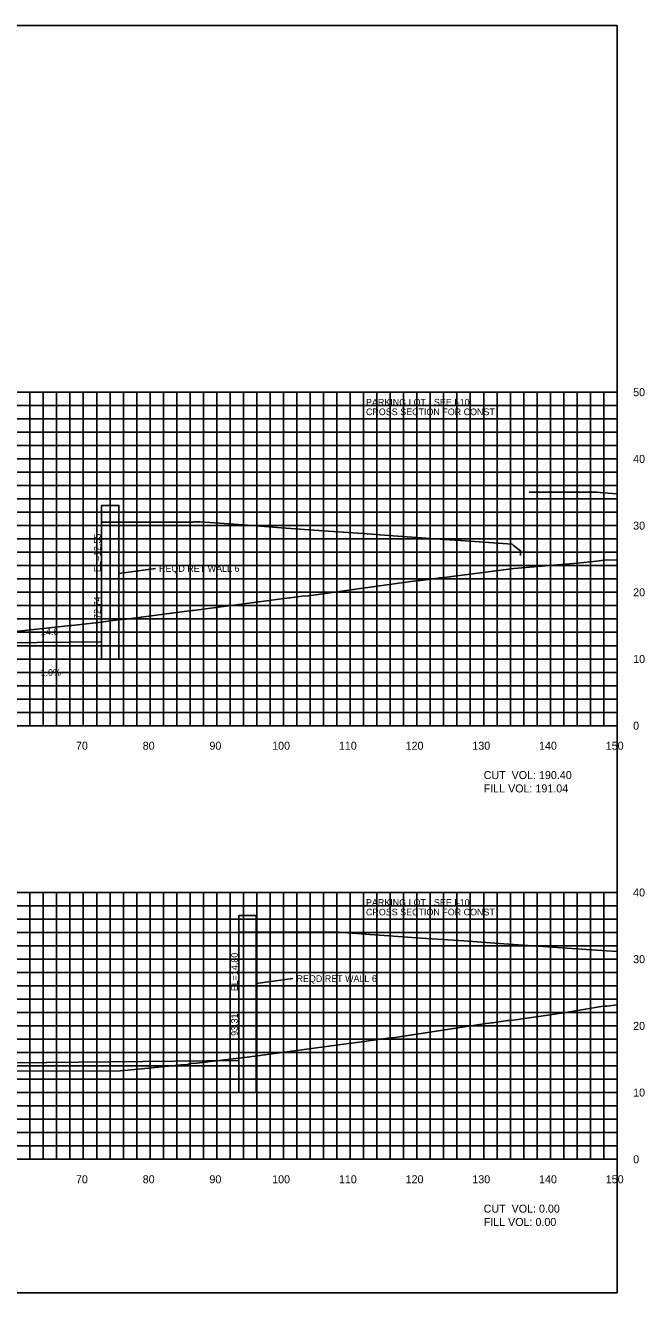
# Model space of a CAD drawing. Extents: x 1797682 to 1802785, y 249453 to 250269.
# Drawn here: x 1802352.3 to 1802445.1, y 250079.4 to 250269.4 of the extents above; entities that cross this region are included whole.
import ezdxf

# ---------------------------------------------------------------- set-up
doc = ezdxf.new("R2010")
doc.units = 0
for name, color, linetype in [('10', 7, 'Continuous'), ('3', 7, 'Continuous'), ('31', 7, 'Continuous'), ('4', 7, 'Continuous'), ('60', 7, 'Continuous'), ('ANNO-TXT', 7, 'Continuous'), ('CL-CNST', 7, 'Continuous'), ('Level 62', 7, 'Continuous'), ('M-ROADS', 7, 'Continuous'), ('WEARING', 7, 'Continuous')]:
    doc.layers.add(name, color=color, linetype=linetype)

msp = doc.modelspace()

# ---------------------------------------------------------------- linework, layer by layer
for p, q in [((1802363.74, 250176.99), (1802363.74, 250178.99)), ((1802384.31, 250114.23), (1802384.31, 250116.23))]:
    msp.add_line(p, q)
msp.add_lwpolyline([(1802141, 250079.43), (1802441, 250079.43), (1802441, 250269.43), (1802141, 250269.43)], close=True)
at = {"layer": '3'}
for p, q in [((1802371.81, 250188), (1802366.33, 250187.26)), ((1802392.4, 250126.52), (1802386.92, 250125.78))]:
    msp.add_line(p, q, dxfattribs=at)
at = {"layer": '60'}
for p, q in [((1802441, 250164.43), (1802441, 250214.43)), ((1802441.06, 250214.43), (1802441, 250214.43)), ((1802441.06, 250204.43), (1802441, 250204.43)), ((1802441.06, 250194.43), (1802441, 250194.43)), ((1802441.06, 250184.43), (1802441, 250184.43)), ((1802441.06, 250174.43), (1802441, 250174.43)), ((1802141, 250164.43), (1802441, 250164.43)), ((1802361, 250164.37), (1802361, 250164.43)), ((1802371, 250164.37), (1802371, 250164.43)), ((1802381, 250164.37), (1802381, 250164.43)), ((1802391, 250164.37), (1802391, 250164.43)), ((1802401, 250164.37), (1802401, 250164.43)), ((1802411, 250164.37), (1802411, 250164.43)), ((1802421, 250164.37), (1802421, 250164.43)), ((1802431, 250164.37), (1802431, 250164.43)), ((1802441, 250164.37), (1802441, 250164.43)), ((1802441.06, 250164.43), (1802441, 250164.43)), ((1802441, 250099.43), (1802441, 250139.43)), ((1802441.06, 250139.43), (1802441, 250139.43)), ((1802441.06, 250129.43), (1802441, 250129.43)), ((1802441.06, 250119.43), (1802441, 250119.43)), ((1802441.06, 250109.43), (1802441, 250109.43)), ((1802141, 250099.43), (1802441, 250099.43)), ((1802361, 250099.37), (1802361, 250099.43)), ((1802371, 250099.37), (1802371, 250099.43)), ((1802381, 250099.37), (1802381, 250099.43)), ((1802391, 250099.37), (1802391, 250099.43)), ((1802401, 250099.37), (1802401, 250099.43)), ((1802411, 250099.37), (1802411, 250099.43)), ((1802421, 250099.37), (1802421, 250099.43)), ((1802431, 250099.37), (1802431, 250099.43)), ((1802441, 250099.37), (1802441, 250099.43)), ((1802441.06, 250099.43), (1802441, 250099.43))]:
    msp.add_line(p, q, dxfattribs=at)
at = {"layer": 'CL-CNST'}
for points in [[(1802366.33, 250194.97), (1802363.74, 250194.97), (1802363.74, 250197.47), (1802366.33, 250197.47)], [(1802363.74, 250174.43), (1802366.33, 250174.43), (1802366.33, 250194.97), (1802363.74, 250194.97)], [(1802386.92, 250133.49), (1802384.31, 250133.49), (1802384.31, 250135.99), (1802386.92, 250135.99)], [(1802384.31, 250109.43), (1802386.92, 250109.43), (1802386.92, 250133.49), (1802384.31, 250133.49)]]:
    msp.add_lwpolyline(points, close=True, dxfattribs=at)
for points in [[(1802366.33, 250194.97), (1802372.49, 250194.95), (1802377.44, 250194.93), (1802377.47, 250194.97), (1802377.51, 250195), (1802378.03, 250195), (1802378.52, 250195), (1802384.3, 250194.58), (1802390.72, 250194.12), (1802395.53, 250193.77), (1802402.91, 250193.24), (1802406.76, 250192.96), (1802415.11, 250192.37), (1802417.52, 250192.19), (1802425.27, 250191.64), (1802425.49, 250191.46), (1802426.54, 250190.67), (1802426.54, 250190.07), (1802426.54, 250189.94)], [(1802234.86, 250176.57), (1802236, 250176.95), (1802237, 250176.99), (1802242, 250177.07), (1802244, 250177.09), (1802244.33, 250177.09), (1802244.5, 250176.59), (1802246.5, 250176.75), (1802291, 250177.73), (1802346.68, 250176.5), (1802348.68, 250176.34), (1802348.85, 250176.84), (1802349.18, 250176.84), (1802363.74, 250176.99)], [(1802386.92, 250133.49), (1802395.6, 250133.47), (1802399.3, 250133.46), (1802404.01, 250133.13), (1802411.67, 250132.6), (1802418.03, 250132.16), (1802424.04, 250131.74), (1802432.08, 250131.18), (1802436.42, 250130.88), (1802441, 250130.56)], [(1802265.51, 250111.95), (1802265.51, 250111.95), (1802269.74, 250113.36), (1802270.74, 250113.4), (1802274.5, 250113.46), (1802274.5, 250113.46), (1802274.51, 250113.46), (1802274.84, 250113.46), (1802274.84, 250113.46), (1802275.01, 250112.97), (1802275.01, 250112.97), (1802276.99, 250113.13), (1802277.01, 250113.12), (1802277.01, 250113.12), (1802291, 250113.43), (1802305, 250113.12), (1802305, 250113.12), (1802307, 250112.96), (1802307, 250112.96), (1802307.16, 250113.46), (1802307.16, 250113.46), (1802307.49, 250113.46), (1802307.52, 250113.46), (1802384.31, 250114.23)]]:
    msp.add_lwpolyline(points, dxfattribs=at)
at = {"layer": 'Level 62'}
for p, q in [((1802141, 250214.43), (1802441, 250214.43)), ((1802353, 250164.43), (1802353, 250214.43)), ((1802355, 250164.43), (1802355, 250214.43)), ((1802357, 250164.43), (1802357, 250214.43)), ((1802359, 250164.43), (1802359, 250214.43)), ((1802361, 250164.43), (1802361, 250214.43)), ((1802363, 250164.43), (1802363, 250214.43)), ((1802365, 250164.43), (1802365, 250214.43)), ((1802367, 250164.43), (1802367, 250214.43)), ((1802369, 250164.43), (1802369, 250214.43)), ((1802371, 250164.43), (1802371, 250214.43)), ((1802373, 250164.43), (1802373, 250214.43)), ((1802375, 250164.43), (1802375, 250214.43)), ((1802377, 250164.43), (1802377, 250214.43)), ((1802379, 250164.43), (1802379, 250214.43)), ((1802381, 250164.43), (1802381, 250214.43)), ((1802383, 250164.43), (1802383, 250214.43)), ((1802385, 250164.43), (1802385, 250214.43)), ((1802387, 250164.43), (1802387, 250214.43)), ((1802389, 250164.43), (1802389, 250214.43)), ((1802391, 250164.43), (1802391, 250214.43)), ((1802393, 250164.43), (1802393, 250214.43)), ((1802395, 250164.43), (1802395, 250214.43)), ((1802397, 250164.43), (1802397, 250214.43)), ((1802399, 250164.43), (1802399, 250214.43)), ((1802401, 250164.43), (1802401, 250214.43)), ((1802403, 250164.43), (1802403, 250214.43)), ((1802405, 250164.43), (1802405, 250214.43)), ((1802407, 250164.43), (1802407, 250214.43)), ((1802409, 250164.43), (1802409, 250214.43)), ((1802411, 250164.43), (1802411, 250214.43)), ((1802413, 250164.43), (1802413, 250214.43)), ((1802415, 250164.43), (1802415, 250214.43)), ((1802417, 250164.43), (1802417, 250214.43)), ((1802419, 250164.43), (1802419, 250214.43)), ((1802421, 250164.43), (1802421, 250214.43)), ((1802423, 250164.43), (1802423, 250214.43)), ((1802425, 250164.43), (1802425, 250214.43)), ((1802427, 250164.43), (1802427, 250214.43)), ((1802429, 250164.43), (1802429, 250214.43)), ((1802431, 250164.43), (1802431, 250214.43)), ((1802433, 250164.43), (1802433, 250214.43)), ((1802435, 250164.43), (1802435, 250214.43)), ((1802437, 250164.43), (1802437, 250214.43)), ((1802439, 250164.43), (1802439, 250214.43)), ((1802441, 250164.43), (1802441, 250214.43)), ((1802141, 250212.43), (1802441, 250212.43)), ((1802141, 250210.43), (1802441, 250210.43)), ((1802141, 250208.43), (1802441, 250208.43)), ((1802141, 250206.43), (1802441, 250206.43)), ((1802141, 250204.43), (1802441, 250204.43)), ((1802141, 250202.43), (1802441, 250202.43)), ((1802141, 250200.43), (1802441, 250200.43)), ((1802141, 250198.43), (1802441, 250198.43)), ((1802141, 250196.43), (1802441, 250196.43)), ((1802141, 250194.43), (1802441, 250194.43)), ((1802141, 250192.43), (1802441, 250192.43)), ((1802141, 250190.43), (1802441, 250190.43)), ((1802141, 250188.43), (1802441, 250188.43)), ((1802141, 250186.43), (1802441, 250186.43)), ((1802141, 250184.43), (1802441, 250184.43)), ((1802141, 250182.43), (1802441, 250182.43)), ((1802141, 250180.43), (1802441, 250180.43)), ((1802141, 250178.43), (1802441, 250178.43)), ((1802141, 250176.43), (1802441, 250176.43)), ((1802141, 250174.43), (1802441, 250174.43)), ((1802141, 250172.43), (1802441, 250172.43)), ((1802141, 250170.43), (1802441, 250170.43)), ((1802141, 250168.43), (1802441, 250168.43)), ((1802141, 250166.43), (1802441, 250166.43)), ((1802141, 250164.43), (1802441, 250164.43)), ((1802141, 250139.43), (1802441, 250139.43)), ((1802353, 250099.43), (1802353, 250139.43)), ((1802355, 250099.43), (1802355, 250139.43)), ((1802357, 250099.43), (1802357, 250139.43)), ((1802359, 250099.43), (1802359, 250139.43)), ((1802361, 250099.43), (1802361, 250139.43)), ((1802363, 250099.43), (1802363, 250139.43)), ((1802365, 250099.43), (1802365, 250139.43)), ((1802367, 250099.43), (1802367, 250139.43)), ((1802369, 250099.43), (1802369, 250139.43)), ((1802371, 250099.43), (1802371, 250139.43)), ((1802373, 250099.43), (1802373, 250139.43)), ((1802375, 250099.43), (1802375, 250139.43)), ((1802377, 250099.43), (1802377, 250139.43)), ((1802379, 250099.43), (1802379, 250139.43)), ((1802381, 250099.43), (1802381, 250139.43)), ((1802383, 250099.43), (1802383, 250139.43)), ((1802385, 250099.43), (1802385, 250139.43)), ((1802387, 250099.43), (1802387, 250139.43)), ((1802389, 250099.43), (1802389, 250139.43)), ((1802391, 250099.43), (1802391, 250139.43)), ((1802393, 250099.43), (1802393, 250139.43)), ((1802395, 250099.43), (1802395, 250139.43)), ((1802397, 250099.43), (1802397, 250139.43)), ((1802399, 250099.43), (1802399, 250139.43)), ((1802401, 250099.43), (1802401, 250139.43)), ((1802403, 250099.43), (1802403, 250139.43)), ((1802405, 250099.43), (1802405, 250139.43)), ((1802407, 250099.43), (1802407, 250139.43)), ((1802409, 250099.43), (1802409, 250139.43)), ((1802411, 250099.43), (1802411, 250139.43)), ((1802413, 250099.43), (1802413, 250139.43)), ((1802415, 250099.43), (1802415, 250139.43)), ((1802417, 250099.43), (1802417, 250139.43)), ((1802419, 250099.43), (1802419, 250139.43)), ((1802421, 250099.43), (1802421, 250139.43)), ((1802423, 250099.43), (1802423, 250139.43)), ((1802425, 250099.43), (1802425, 250139.43)), ((1802427, 250099.43), (1802427, 250139.43)), ((1802429, 250099.43), (1802429, 250139.43)), ((1802431, 250099.43), (1802431, 250139.43)), ((1802433, 250099.43), (1802433, 250139.43)), ((1802435, 250099.43), (1802435, 250139.43)), ((1802437, 250099.43), (1802437, 250139.43)), ((1802439, 250099.43), (1802439, 250139.43)), ((1802441, 250099.43), (1802441, 250139.43)), ((1802141, 250137.43), (1802441, 250137.43)), ((1802141, 250135.43), (1802441, 250135.43)), ((1802141, 250133.43), (1802441, 250133.43)), ((1802141, 250131.43), (1802441, 250131.43)), ((1802141, 250129.43), (1802441, 250129.43)), ((1802141, 250127.43), (1802441, 250127.43)), ((1802141, 250125.43), (1802441, 250125.43)), ((1802141, 250123.43), (1802441, 250123.43)), ((1802141, 250121.43), (1802441, 250121.43)), ((1802141, 250119.43), (1802441, 250119.43)), ((1802141, 250117.43), (1802441, 250117.43)), ((1802141, 250115.43), (1802441, 250115.43)), ((1802141, 250113.43), (1802441, 250113.43)), ((1802141, 250111.43), (1802441, 250111.43)), ((1802141, 250109.43), (1802441, 250109.43)), ((1802141, 250107.43), (1802441, 250107.43)), ((1802141, 250105.43), (1802441, 250105.43)), ((1802141, 250103.43), (1802441, 250103.43)), ((1802141, 250101.43), (1802441, 250101.43)), ((1802141, 250099.43), (1802441, 250099.43))]:
    msp.add_line(p, q, dxfattribs=at)
at = {"layer": 'M-ROADS'}
for points in [[(1802347.6, 250178.22), (1802359.07, 250179.47), (1802359.28, 250179.47), (1802359.74, 250179.49), (1802362.82, 250179.85), (1802362.9, 250179.85), (1802366.52, 250180.33), (1802366.78, 250180.35), (1802367.42, 250180.42), (1802377.24, 250181.69), (1802377.48, 250181.68), (1802391.11, 250183.51), (1802391.87, 250183.59), (1802392, 250183.6), (1802394.13, 250183.88), (1802394.47, 250183.87), (1802402.52, 250185.01), (1802411.17, 250186.22), (1802411.52, 250186.21), (1802414.18, 250186.56), (1802414.37, 250186.58), (1802415.1, 250186.66), (1802425.54, 250187.98), (1802435.05, 250188.82), (1802437.92, 250189.11), (1802439.07, 250189.23), (1802441, 250189.3)], [(1802347.57, 250112.65), (1802366.51, 250112.69), (1802367.08, 250112.72), (1802367.18, 250112.73), (1802375.24, 250113.56), (1802375.69, 250113.57), (1802375.78, 250113.57), (1802376.58, 250113.62), (1802377.16, 250113.79), (1802377.5, 250113.82), (1802377.56, 250113.81), (1802385.95, 250114.79), (1802391.89, 250115.57), (1802400.72, 250116.79), (1802401.25, 250116.86), (1802407.01, 250117.65), (1802407.13, 250117.64), (1802407.4, 250117.63), (1802421.37, 250119.78), (1802422.22, 250119.89), (1802422.3, 250119.9), (1802423.64, 250120.09), (1802424.5, 250120.22), (1802425.02, 250120.23), (1802425.09, 250120.24), (1802433.02, 250121.4), (1802438.92, 250122.36), (1802439.34, 250122.37), (1802439.48, 250122.37), (1802441, 250122.59)]]:
    msp.add_lwpolyline(points, dxfattribs=at)
at = {"layer": 'WEARING'}
msp.add_lwpolyline([(1802427.81, 250199.44), (1802429.34, 250199.44), (1802437.97, 250199.42), (1802438.94, 250199.35), (1802441, 250199.2)], dxfattribs=at)

# ---------------------------------------------------------------- texts
at = {"layer": '10'}
for s, p in [('70', (1802359.9, 250160.83)), ('80', (1802369.9, 250160.83)), ('90', (1802379.9, 250160.83)), ('100', (1802389.3, 250160.83)), ('110', (1802399.3, 250160.83)), ('120', (1802409.3, 250160.83)), ('130', (1802419.3, 250160.83)), ('140', (1802429.3, 250160.83)), ('150', (1802439.3, 250160.83)), ('70', (1802359.9, 250095.83)), ('80', (1802369.9, 250095.83)), ('90', (1802379.9, 250095.83)), ('100', (1802389.3, 250095.83)), ('110', (1802399.3, 250095.83)), ('120', (1802409.3, 250095.83)), ('130', (1802419.3, 250095.83)), ('140', (1802429.3, 250095.83)), ('150', (1802439.3, 250095.83))]:
    msp.add_text(s, height=1.2, dxfattribs=at).set_placement(p)
at = {"layer": '3'}
for s, p in [('PARKING LOT - SEE I-10', (1802403.36, 250212.43)), ('CROSS SECTION FOR CONST ', (1802403.36, 250210.99)), ('REQD RET WALL 6', (1802372.35, 250187.5)), ('CROSS SECTION FOR CONST ', (1802403.36, 250135.99)), ('PARKING LOT - SEE I-10', (1802403.36, 250137.43)), ('REQD RET WALL 6', (1802392.95, 250126.02))]:
    msp.add_text(s, height=1, dxfattribs=at).set_placement(p)
for s, p in [('EL=12.55', (1802363.59, 250187.46)), ('72.74', (1802363.59, 250180.44)), ('EL=14.80', (1802384.16, 250124.63)), ('93.31', (1802384.16, 250117.93))]:
    msp.add_text(s, height=1, rotation=90, dxfattribs=at).set_placement(p)
at = {"layer": '31'}
for s, p in [('50', (1802443.4, 250213.83)), ('40', (1802443.4, 250203.83)), ('30', (1802443.4, 250193.83)), ('20', (1802443.4, 250183.83)), ('10', (1802443.4, 250173.83)), ('0', (1802443.4, 250163.83)), ('40', (1802443.4, 250138.83)), ('30', (1802443.4, 250128.83)), ('20', (1802443.4, 250118.83)), ('10', (1802443.4, 250108.83)), ('0', (1802443.4, 250098.83))]:
    msp.add_text(s, height=1.2, dxfattribs=at).set_placement(p)
at = {"layer": '4'}
for s, p in [('14.6', (1802354.65, 250178)), ('1.0%', (1802354.6, 250171.89))]:
    msp.add_text(s, height=1, rotation=0.5729, dxfattribs=at).set_placement(p)
at = {"layer": 'ANNO-TXT'}
for s, p in [('CUT  VOL: 190.40', (1802421, 250156.43)), ('FILL VOL: 191.04', (1802421, 250154.43)), ('CUT  VOL: 0.00', (1802421, 250091.43)), ('FILL VOL: 0.00', (1802421, 250089.43))]:
    msp.add_text(s, height=1.2, dxfattribs=at).set_placement(p)

doc.saveas('drawing.dxf')
